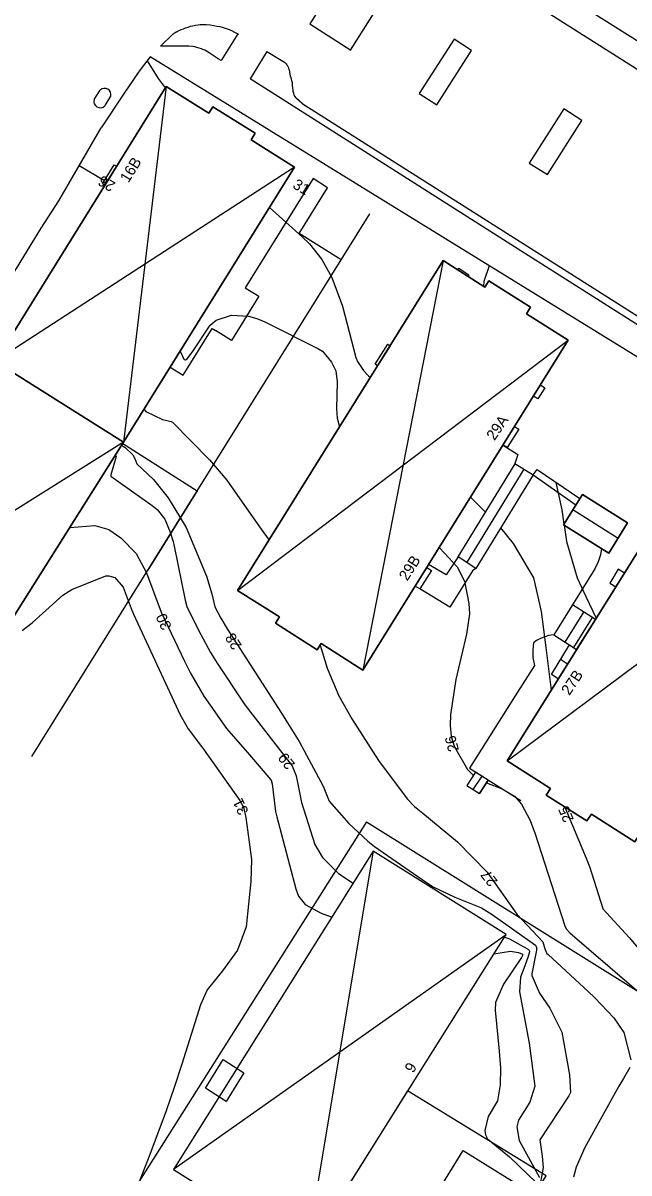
# Model space of a CAD drawing. Extents: x 67169 to 69652, y 20189 to 22818.
# Drawn here: x 69252.8 to 69308.9, y 21145.5 to 21251.9 of the extents above; entities that cross this region are included whole.
import ezdxf

# ---------------------------------------------------------------- set-up
doc = ezdxf.new("R2010")
doc.units = 0
for name, color, linetype in [('BYGGNAD_HUSLIV', 7, 'Continuous'), ('BYGGNAD_HUSLIV 11', 7, 'Continuous'), ('BYGGNADSDETALJER', 7, 'Continuous'), ('BYGGNADSDETALJER 19', 7, 'Continuous'), ('BYGGNADSSYMBOLER', 7, 'Continuous'), ('BYGGNADSSYMBOLER 30', 7, 'Continuous'), ('HOJDKURVOR_2014', 7, 'Continuous'), ('HOJDKURVOR_2014 5M', 7, 'Continuous'), ('HOJDKURVOR_TEXTER_2014', 7, 'Continuous'), ('Instruktioner', 7, 'Continuous'), ('MUR_STAKET', 7, 'Continuous'), ('MUR_STAKET_SYMBOL', 7, 'Continuous'), ('Std_Ritningsstämpel', 7, 'Continuous'), ('VAGAR 121', 7, 'Continuous'), ('VAGAR 123', 7, 'Continuous')]:
    doc.layers.add(name, color=color, linetype=linetype)

msp = doc.modelspace()

# ---------------------------------------------------------------- linework, layer by layer
at = {"layer": 'BYGGNAD_HUSLIV'}
for points in [[(69266.07, 21246.03), (69270.03, 21243.54), (69270.4, 21244.14), (69274.3, 21241.69), (69273.93, 21241.1), (69277.96, 21238.56), (69262.14, 21213.11), (69250.25, 21220.58), (69266.07, 21246.03)], [(69291.69, 21229.91), (69295.55, 21227.45), (69295.93, 21228.04), (69299.78, 21225.59), (69299.4, 21225), (69303.27, 21222.55), (69284.27, 21192.03), (69280.4, 21194.49), (69280.03, 21193.9), (69276.18, 21196.35), (69276.56, 21196.94), (69272.69, 21199.4), (69291.69, 21229.91)], [(69243.03, 21209.08), (69250.25, 21220.58), (69262.14, 21213.11), (69246.7, 21188.62), (69243.05, 21190.91)], [(69316.67, 21214.12), (69320.72, 21211.55), (69321.12, 21212.18), (69324.91, 21209.84), (69324.48, 21209.17), (69328.5, 21206.63), (69309.43, 21176.14), (69305.4, 21178.7), (69304.99, 21178.06), (69301.22, 21180.45), (69301.63, 21181.08), (69297.6, 21183.63), (69316.67, 21214.12)], [(69304.57, 21208.28), (69308.75, 21205.64), (69307.01, 21202.84), (69302.83, 21205.47), (69304.57, 21208.28)], [(69271.34, 21156), (69273.27, 21154.75), (69271.64, 21152.09), (69269.7, 21153.33), (69271.34, 21156)], [(69293.56, 21147.57), (69301.05, 21142.9), (69292.91, 21129.74), (69285.43, 21134.41), (69293.56, 21147.57)]]:
    msp.add_lwpolyline(points, dxfattribs=at)
at = {"layer": 'BYGGNAD_HUSLIV 11'}
for points in [[(69266.07, 21246.03), (69270.03, 21243.54), (69270.4, 21244.14), (69274.3, 21241.69), (69273.93, 21241.1), (69277.96, 21238.56), (69262.14, 21213.11), (69250.25, 21220.58), (69266.07, 21246.03)], [(69291.69, 21229.91), (69295.55, 21227.45), (69295.93, 21228.04), (69299.78, 21225.59), (69299.4, 21225), (69303.27, 21222.55), (69284.27, 21192.03), (69280.4, 21194.49), (69280.03, 21193.9), (69276.18, 21196.35), (69276.56, 21196.94), (69272.69, 21199.4), (69291.69, 21229.91)], [(69243.03, 21209.08), (69250.25, 21220.58), (69262.14, 21213.11), (69246.7, 21188.62), (69243.05, 21190.91)], [(69316.67, 21214.12), (69320.72, 21211.55), (69321.12, 21212.18), (69324.91, 21209.84), (69324.48, 21209.17), (69328.5, 21206.63), (69309.43, 21176.14), (69305.4, 21178.7), (69304.99, 21178.06), (69301.22, 21180.45), (69301.63, 21181.08), (69297.6, 21183.63), (69316.67, 21214.12)]]:
    msp.add_lwpolyline(points, dxfattribs=at)
at = {"layer": 'BYGGNADSDETALJER'}
msp.add_line((69305.49, 21196.88), (69303.76, 21194.11), dxfattribs=at)
for points in [[(69261.27, 21238.77), (69261.48, 21238.64), (69260.38, 21236.88), (69260.18, 21237.01), (69261.27, 21238.77)], [(69293.15, 21229.21), (69294.08, 21228.6), (69293.99, 21228.45), (69293.05, 21229.05), (69293.15, 21229.21)], [(69285.42, 21220.34), (69286.57, 21222.18), (69286.79, 21222.04), (69285.63, 21220.18), (69285.42, 21220.34)], [(69301.09, 21218.15), (69300.45, 21217.11), (69300.04, 21217.37), (69300.69, 21218.42), (69301.09, 21218.15)], [(69297.6, 21212.61), (69297.23, 21212.85), (69298.3, 21214.56), (69298.68, 21214.33), (69297.6, 21212.61)], [(69298.33, 21211.13), (69300.02, 21210.09), (69294.72, 21201.42), (69293.07, 21202.49), (69298.34, 21211.12)], [(69289.11, 21199.8), (69290.17, 21201.5), (69290.61, 21201.23), (69289.55, 21199.53), (69289.11, 21199.8)], [(69307.67, 21199.74), (69308.46, 21201), (69307.89, 21201.35), (69307.12, 21200.08), (69307.67, 21199.74)], [(69304.04, 21193.94), (69305.77, 21196.7), (69303.65, 21198.06), (69301.92, 21195.27), (69304.04, 21193.94)], [(69303.37, 21194.36), (69304.04, 21193.94), (69302.33, 21191.2), (69301.7, 21191.61), (69303.37, 21194.36)], [(69295.87, 21181.84), (69294.7, 21182.58), (69293.88, 21181.34), (69295.07, 21180.61), (69295.87, 21181.84)]]:
    msp.add_lwpolyline(points, dxfattribs=at)
at = {"layer": 'BYGGNADSDETALJER 19'}
msp.add_line((69305.49, 21196.88), (69303.76, 21194.11), dxfattribs=at)
for points in [[(69298.33, 21211.13), (69300.02, 21210.09), (69294.72, 21201.42), (69293.07, 21202.49), (69298.34, 21211.12)], [(69304.04, 21193.94), (69305.77, 21196.7), (69303.65, 21198.06), (69301.92, 21195.27), (69304.04, 21193.94)], [(69295.87, 21181.84), (69294.7, 21182.58), (69293.88, 21181.34), (69295.07, 21180.61), (69295.87, 21181.84)]]:
    msp.add_lwpolyline(points, dxfattribs=at)
at = {"layer": 'BYGGNADSSYMBOLER'}
for p, q in [((69266.07, 21246.03), (69262.14, 21213.11)), ((69277.96, 21238.56), (69250.25, 21220.58)), ((69291.69, 21229.91), (69284.27, 21192.03)), ((69272.69, 21199.4), (69303.27, 21222.55)), ((69293.89, 21201.95), (69299.18, 21210.61)), ((69303.7, 21206.88), (69307.88, 21204.24)), ((69297.6, 21183.63), (69328.5, 21206.63)), ((69293.89, 21201.95), (69293.89, 21201.95)), ((69302.98, 21194.6), (69304.71, 21197.38)), ((69302.98, 21194.6), (69302.98, 21194.6)), ((69303.19, 21192.57), (69302.54, 21192.99)), ((69303.18, 21192.57), (69303.18, 21192.57)), ((69294.47, 21180.98), (69295.29, 21182.21)), ((69294.47, 21180.98), (69294.47, 21180.98)), ((69285.23, 21175.26), (69279.02, 21138.12)), ((69266.75, 21145.84), (69297.52, 21167.57))]:
    msp.add_line(p, q, dxfattribs=at)
msp.add_lwpolyline([(69262.14, 21213.11), (69243.04, 21201.16), (69234.83, 21196.03)], dxfattribs=at)
at = {"layer": 'BYGGNADSSYMBOLER 30'}
for p, q in [((69266.07, 21246.03), (69262.14, 21213.11)), ((69277.96, 21238.56), (69250.25, 21220.58)), ((69291.69, 21229.91), (69284.27, 21192.03)), ((69272.69, 21199.4), (69303.27, 21222.55)), ((69297.6, 21183.63), (69328.5, 21206.63)), ((69285.23, 21175.26), (69279.02, 21138.12)), ((69266.75, 21145.84), (69297.52, 21167.57))]:
    msp.add_line(p, q, dxfattribs=at)
msp.add_lwpolyline([(69262.14, 21213.11), (69243.04, 21201.16), (69234.83, 21196.03)], dxfattribs=at)
at = {"layer": 'HOJDKURVOR_2014'}
for p, q in [((69258.03, 21238.7), (69260.38, 21237.33)), ((69260.58, 21237.21), (69260.59, 21237.21))]:
    msp.add_line(p, q, dxfattribs=at)
for points in [[(69295.94, 21229.43), (69295.46, 21227.97), (69295.42, 21227.54)], [(69267.37, 21221.52), (69267.7, 21220.79), (69267.74, 21220.75), (69267.86, 21220.73), (69268.03, 21220.81), (69268.5, 21221.48), (69270.15, 21223.94), (69270.71, 21224.4), (69272.12, 21224.86), (69273.69, 21224.77), (69274.45, 21224.55), (69275.19, 21224.26), (69280.17, 21221.76), (69280.54, 21221.52), (69281.38, 21220.53), (69281.76, 21219.71), (69281.88, 21218.7), (69281.82, 21216.2), (69281.9, 21215.32), (69282.12, 21214.54)], [(69264.03, 21216.15), (69264.2, 21215.94), (69265.73, 21215.22), (69266.54, 21215.03), (69266.65, 21214.97), (69270.09, 21211.48), (69271.7, 21209.59), (69273.11, 21207.55), (69274.86, 21205.07), (69275.59, 21204.04)], [(69261.96, 21212.82), (69262.28, 21212.61), (69263.01, 21211.94), (69263.18, 21211.6), (69263.38, 21211.1), (69264.91, 21209.67), (69266.26, 21207.97), (69267.94, 21205.21), (69269.8, 21200.7), (69270.29, 21199.09), (69270.59, 21197.89), (69271.14, 21196.83), (69271.73, 21195.84), (69276.74, 21188.03), (69277.16, 21187.38), (69278.39, 21185.42), (69280.6, 21181.27), (69281.16, 21179.89), (69282.97, 21177.82), (69284.72, 21176.19), (69285.36, 21175.71), (69290.14, 21172.36), (69290.76, 21171.96), (69292.77, 21171.01), (69295.24, 21170.02), (69296.24, 21169.42), (69300.23, 21166.56), (69300.34, 21166.34), (69300.34, 21166.1), (69299.89, 21163.92), (69299.89, 21163.77), (69300.6, 21162.14), (69301.56, 21160.75), (69302.67, 21158.53), (69303.39, 21154.56), (69303.46, 21152.93), (69303.32, 21152.64), (69300.65, 21148.55), (69300.86, 21147.06), (69300.95, 21146.01), (69300.59, 21144.09)], [(69261.38, 21211.9), (69261.43, 21211.84), (69261.44, 21211.81), (69261.44, 21211.78), (69260.95, 21210.1), (69260.96, 21209.98), (69264.78, 21207.25), (69265.23, 21206.89), (69265.96, 21206), (69266.46, 21204.78), (69266.71, 21203.93), (69266.81, 21203.5), (69267.82, 21198.49), (69267.98, 21197.92), (69269.06, 21195.71), (69270.17, 21193.66), (69270.78, 21192.66), (69273.35, 21188.8), (69276, 21185.38), (69277.74, 21183.16), (69278.09, 21182.24), (69278.6, 21179.76), (69279.84, 21175.88), (69280.55, 21174.68), (69282, 21173.2), (69283.37, 21172.3)], [(69302.13, 21209.39), (69302.68, 21206.85), (69302.86, 21205.54)], [(69302.88, 21205.44), (69303.09, 21203.92), (69304.09, 21200.55), (69304.88, 21198.84), (69305.85, 21196.83)], [(69291.32, 21203.36), (69291.39, 21203.3), (69292.98, 21201.58), (69293.67, 21200.24), (69294.08, 21198.18), (69294.12, 21197.23), (69293.86, 21195.34), (69292.88, 21191.16), (69292.36, 21187.91), (69292.33, 21186.89), (69292.43, 21185.88), (69292.74, 21184.93), (69293.95, 21182.83), (69294.41, 21182.35), (69294.51, 21182.29)], [(69252.76, 21195.69), (69253.69, 21196.4), (69256.51, 21198.95), (69257.36, 21199.48), (69260.49, 21200.73), (69260.77, 21200.75), (69261.32, 21200.58), (69262.09, 21199.68), (69262.85, 21197.71), (69263.07, 21197.19), (69267.18, 21188.27), (69267.36, 21187.89), (69268.12, 21186.6), (69269.36, 21184.94), (69269.53, 21184.7), (69272.89, 21179.94), (69272.96, 21179.82), (69273.22, 21179.33), (69273.46, 21178.38), (69273.97, 21174.51), (69273.92, 21172.47), (69273.49, 21168.27), (69272.66, 21166.1), (69271.29, 21164.2), (69269.87, 21162.43), (69269.25, 21161.06), (69267.52, 21155.57), (69266.81, 21153.39), (69266.07, 21151.23), (69264.48, 21146.95), (69262.78, 21142.63)], [(69280.31, 21194.34), (69280.98, 21192.19), (69282.05, 21189.64), (69283.25, 21187.51), (69285.7, 21183.67), (69288.36, 21180.1), (69289.03, 21179.39), (69289.81, 21178.77), (69293.01, 21176.14), (69295.75, 21173.33), (69298.5, 21169.45), (69300.91, 21166.89), (69301.11, 21166.24), (69301.29, 21165.81), (69301.4, 21165.69), (69305.11, 21162.28), (69305.73, 21161.69), (69307.48, 21159.86), (69308.41, 21158.5), (69309.05, 21155.95)], [(69295.71, 21181.6), (69297.15, 21181.02), (69298.29, 21180.35), (69298.93, 21179.61), (69299.74, 21178.09), (69299.97, 21177.53), (69300.17, 21176.97), (69302.96, 21168.37), (69303.08, 21168.09), (69303.42, 21167.7), (69310.86, 21161.3), (69311.83, 21160.38), (69313.34, 21158.58), (69313.95, 21157.8), (69314.13, 21157.5), (69314.22, 21157.19), (69314.21, 21157.03), (69313.63, 21155.67), (69313.08, 21154.22), (69313.05, 21153.66), (69313.46, 21152.57), (69313.93, 21151.91)], [(69297.36, 21167.32), (69297.84, 21167.15), (69299.59, 21166.17), (69299.62, 21166.14), (69299.69, 21166.01), (69299.69, 21165.96), (69299.54, 21165.44), (69299.16, 21164.42), (69298.86, 21163.62), (69298.75, 21162.26), (69299.65, 21157.51), (69300.17, 21153.53), (69299.7, 21152.05), (69298.67, 21150.38), (69298.51, 21149.76), (69298.72, 21148.49), (69300.61, 21145.06)], [(69308.97, 21155.26), (69308.37, 21154.24), (69307.95, 21153.53), (69304.8, 21147.85), (69304.01, 21146.04), (69303.76, 21145.09)]]:
    msp.add_lwpolyline(points, dxfattribs=at)
at = {"layer": 'HOJDKURVOR_2014 5M'}
for points in [[(69264.32, 21248.39), (69265.33, 21246.77), (69265.99, 21245.9)], [(69275.64, 21234.84), (69278.66, 21232.12), (69279.32, 21231.46), (69280.48, 21230), (69281.4, 21228.36), (69282.37, 21225.71), (69283.63, 21220.96), (69283.77, 21220.58), (69284.34, 21219.73), (69284.94, 21219.07)], [(69294.23, 21208.03), (69294.86, 21207.39), (69295.61, 21206.65)], [(69257.17, 21205.22), (69259.49, 21205.41), (69260.77, 21205.03), (69261.89, 21204.27), (69263.3, 21202.82), (69264.26, 21201.03), (69265.6, 21197.39), (69267.78, 21192.84), (69268.34, 21191.75), (69269.55, 21189.62), (69271.65, 21186.61), (69273.79, 21184.17), (69275.76, 21181.87), (69275.79, 21181.83), (69275.88, 21181.5), (69276.2, 21178.95), (69276.32, 21178.43), (69278.06, 21171.79), (69278.33, 21171.09), (69278.93, 21170.34), (69280.42, 21169.52), (69281.34, 21169.2), (69281.41, 21169.18)], [(69297.01, 21205.18), (69298.16, 21203.75), (69300.05, 21200.56), (69300.77, 21197.43), (69301.19, 21194.11), (69301.67, 21190.15)], [(69302.95, 21179.35), (69304.93, 21174.61), (69305.23, 21173.85), (69306.45, 21169.96), (69306.46, 21169.94), (69308.91, 21167.29), (69310.39, 21165.51), (69311.09, 21164.58), (69315.18, 21158.97), (69315.21, 21158.93), (69315.36, 21158.76), (69316.11, 21158.38), (69316.71, 21158.2)], [(69296.38, 21165.76), (69297.92, 21166), (69298.67, 21165.9), (69299.02, 21165.73), (69299.05, 21165.67), (69298.95, 21165.42), (69297.28, 21162.96), (69296.55, 21161.27), (69296.49, 21160.54), (69296.87, 21156.77), (69297.01, 21155.2), (69296.97, 21153.64), (69296.72, 21152.18), (69295.86, 21150.73), (69295.55, 21149.41), (69295.61, 21149.01), (69295.8, 21148.66), (69297.82, 21146.97), (69300.31, 21144.61)]]:
    msp.add_lwpolyline(points, dxfattribs=at)
at = {"layer": 'MUR_STAKET'}
for p, q in [((69300.02, 21210.09), (69303.97, 21207.32)), ((69294.7, 21182.58), (69293.88, 21181.34)), ((69295.87, 21181.84), (69295.07, 21180.61)), ((69284.59, 21177.99), (69263.19, 21144.09))]:
    msp.add_line(p, q, dxfattribs=at)
for points in [[(69296.1, 21258.84), (69302.52, 21254.78), (69308.5, 21251), (69318.67, 21244.59), (69325.22, 21240.45), (69336.99, 21232.99), (69342.36, 21229.57), (69352.6, 21223.18), (69355.62, 21221.19), (69360.68, 21217.97), (69370.52, 21211.77), (69376.01, 21208.27), (69380.2, 21208.31), (69385.38, 21216.32)], [(69253.66, 21184.04), (69269.07, 21208.8), (69284.9, 21234.23)], [(69266.45, 21220.05), (69267.64, 21219.31), (69270.33, 21223.64), (69270.63, 21223.46)], [(69262.06, 21212.98), (69268.95, 21208.6), (69264.38, 21201.28)], [(69305.73, 21201.39), (69301.92, 21195.27), (69301.43, 21195.22), (69300.76, 21194.97), (69300.33, 21194.76), (69300.04, 21194.53), (69299.98, 21193.87), (69299.98, 21193.2), (69300.13, 21192.46), (69298.36, 21189.65), (69294.13, 21182.95), (69298.87, 21179.95)], [(69284.59, 21177.99), (69309.53, 21162.41), (69316.52, 21157.9)]]:
    msp.add_lwpolyline(points, dxfattribs=at)
at = {"layer": 'MUR_STAKET_SYMBOL'}
for p, q in [((69308.5, 21251), (69308.5, 21251)), ((69308.5, 21251), (69308.5, 21251)), ((69281.24, 21228.36), (69281.24, 21228.36)), ((69269.76, 21222.73), (69269.76, 21222.73)), ((69270.63, 21223.46), (69270.63, 21223.46)), ((69269.11, 21221.67), (69269.11, 21221.67)), ((69268.52, 21220.73), (69268.52, 21220.73)), ((69266.79, 21219.84), (69266.79, 21219.84)), ((69267.85, 21219.66), (69267.85, 21219.66)), ((69267.46, 21219.42), (69267.46, 21219.42)), ((69273.25, 21215.52), (69273.25, 21215.52)), ((69263.18, 21212.27), (69263.18, 21212.27)), ((69264.46, 21211.45), (69264.46, 21211.45)), ((69265.76, 21210.63), (69265.76, 21210.63)), ((69266.99, 21209.85), (69266.99, 21209.85)), ((69268.31, 21209), (69268.31, 21209)), ((69301.56, 21209.01), (69301.56, 21209.01)), ((69268.33, 21207.62), (69268.33, 21207.62)), ((69267.58, 21206.41), (69267.58, 21206.41)), ((69266.79, 21205.15), (69266.79, 21205.15)), ((69265.99, 21203.87), (69265.99, 21203.87)), ((69266.42, 21204.54), (69266.42, 21204.54)), ((69265.21, 21202.61), (69265.21, 21202.61)), ((69264.38, 21201.28), (69264.38, 21201.28)), ((69305.73, 21201.39), (69305.73, 21201.39)), ((69304.96, 21200.16), (69304.96, 21200.16)), ((69304.14, 21198.85), (69304.14, 21198.85)), ((69303.34, 21197.56), (69303.34, 21197.56)), ((69302.6, 21196.38), (69302.6, 21196.38)), ((69301.39, 21195.21), (69301.39, 21195.21)), ((69300.23, 21194.68), (69300.23, 21194.68)), ((69299.98, 21193.81), (69299.98, 21193.81)), ((69258.57, 21191.93), (69258.57, 21191.93)), ((69299.98, 21192.23), (69299.98, 21192.23)), ((69299.16, 21190.94), (69299.16, 21190.94)), ((69298.38, 21189.68), (69298.38, 21189.68)), ((69297.57, 21188.41), (69297.57, 21188.41)), ((69296.8, 21187.19), (69296.8, 21187.19)), ((69295.99, 21185.89), (69295.99, 21185.89)), ((69295.18, 21184.62), (69295.18, 21184.62)), ((69294.39, 21183.36), (69294.39, 21183.36)), ((69293.88, 21181.34), (69293.88, 21181.34)), ((69294.37, 21182.08), (69294.37, 21182.08)), ((69295.53, 21181.32), (69295.53, 21181.32)), ((69295.07, 21180.61), (69295.07, 21180.61)), ((69297.28, 21180.94), (69297.28, 21180.94)), ((69298.51, 21180.16), (69298.51, 21180.16)), ((69281.84, 21173.6), (69281.84, 21173.6)), ((69292.96, 21172.76), (69292.96, 21172.76)), ((69302.19, 21166.99), (69302.19, 21166.99)), ((69275.67, 21163.79), (69275.67, 21163.79)), ((69269.18, 21153.59), (69269.18, 21153.59))]:
    msp.add_line(p, q, dxfattribs=at)
at = {"layer": 'Std_Ritningsstämpel'}
for points in [[(69266.07, 21246.03), (69250.25, 21220.58), (69262.14, 21213.11), (69277.96, 21238.56), (69273.93, 21241.1), (69274.3, 21241.69), (69270.4, 21244.14), (69270.03, 21243.54)], [(69291.69, 21229.91), (69272.69, 21199.4), (69276.56, 21196.94), (69276.18, 21196.35), (69280.03, 21193.9), (69280.4, 21194.49), (69284.27, 21192.03), (69303.27, 21222.55), (69299.4, 21225), (69299.78, 21225.59), (69295.93, 21228.04), (69295.55, 21227.45)], [(69250.25, 21220.58), (69243.03, 21209.08), (69234.83, 21196.03), (69243.05, 21190.91), (69246.7, 21188.62), (69262.14, 21213.11)], [(69316.67, 21214.12), (69297.6, 21183.63), (69301.63, 21181.08), (69301.22, 21180.45), (69304.99, 21178.06), (69305.4, 21178.7), (69309.43, 21176.14), (69328.5, 21206.63), (69324.48, 21209.17), (69324.91, 21209.84), (69321.12, 21212.18), (69320.72, 21211.55)], [(69304.57, 21208.28), (69302.83, 21205.47), (69307.01, 21202.84), (69308.75, 21205.64)], [(69266.76, 21145.82), (69279.02, 21138.11), (69297.52, 21167.57), (69285.23, 21175.26)], [(69279.02, 21138.11), (69291.73, 21130.03), (69301.23, 21145.21), (69288.39, 21153.08)]]:
    msp.add_lwpolyline(points, close=True, dxfattribs=at)
at = {"layer": 'VAGAR 121'}
for p, q in [((69272.7, 21250.9), (69271.15, 21248.42)), ((69376.14, 21179.98), (69264.59, 21248.76)), ((69275.39, 21249.27), (69273.84, 21246.73)), ((69298.62, 21230.97), (69273.84, 21246.73)), ((69259.43, 21244.82), (69259.97, 21245.67)), ((69260.94, 21245.12), (69260.4, 21244.25)), ((69310.95, 21223.94), (69278.89, 21244.25)), ((69331.52, 21210.09), (69298.62, 21230.97))]:
    msp.add_line(p, q, dxfattribs=at)
for points in [[(69313.16, 21245.38), (69298.29, 21254.81), (69295.63, 21256.45), (69293.87, 21257.57), (69257.76, 21280.45), (69248.82, 21286.11), (69242.96, 21289.82), (69226.82, 21300.08), (69172.15, 21334.79)], [(69283.11, 21249.37), (69286.27, 21254.38), (69282.55, 21256.84), (69279.37, 21251.81), (69283.15, 21249.4)], [(69265.56, 21249.75), (69266.7, 21250.85), (69266.76, 21250.9), (69266.82, 21250.95), (69266.88, 21250.99), (69266.99, 21251.07), (69267.09, 21251.12), (69267.19, 21251.17), (69267.35, 21251.25), (69267.48, 21251.3), (69267.68, 21251.37), (69267.87, 21251.44), (69268.11, 21251.52), (69268.32, 21251.59), (69268.5, 21251.63), (69268.66, 21251.67), (69268.8, 21251.7), (69269.05, 21251.74), (69269.23, 21251.76), (69269.37, 21251.77), (69269.58, 21251.77), (69269.78, 21251.76), (69270.15, 21251.72), (69270.48, 21251.67), (69270.77, 21251.62), (69271.03, 21251.56), (69271.25, 21251.51), (69271.63, 21251.39), (69271.91, 21251.29), (69272.11, 21251.2), (69272.41, 21251.06), (69272.7, 21250.9), (69272.76, 21250.86)], [(69289.48, 21245.36), (69291.1, 21244.32), (69294.33, 21249.34), (69292.7, 21250.39), (69289.48, 21245.36)], [(69271.15, 21248.42), (69270.9, 21248.57), (69270.04, 21249.14), (69269.82, 21249.28), (69269.65, 21249.37), (69269.52, 21249.43), (69269.33, 21249.51), (69269.13, 21249.58), (69268.92, 21249.64), (69268.72, 21249.68), (69268.53, 21249.71), (69268.17, 21249.74), (69267.85, 21249.76), (69267.28, 21249.77), (69266.42, 21249.74), (69265.99, 21249.74), (69265.56, 21249.75)], [(69264.59, 21248.76), (69263.78, 21247.68), (69263.38, 21247.14), (69262.99, 21246.59), (69262.24, 21245.51), (69260.08, 21242.21)], [(69275.39, 21249.27), (69277.01, 21248.27), (69277.05, 21248.24), (69277.12, 21248.17), (69277.19, 21248.11), (69277.24, 21248.04), (69277.28, 21247.97), (69277.32, 21247.9), (69277.35, 21247.83), (69277.4, 21247.7), (69277.44, 21247.58), (69277.49, 21247.36), (69277.56, 21247.02), (69277.6, 21246.86), (69277.65, 21246.7), (69277.68, 21246.59), (69277.7, 21246.49), (69277.72, 21246.38), (69277.74, 21246.18), (69277.77, 21245.83), (69277.79, 21245.7), (69277.8, 21245.59), (69277.82, 21245.49), (69277.84, 21245.41), (69277.86, 21245.34), (69277.91, 21245.23), (69277.95, 21245.14), (69277.98, 21245.09), (69278.04, 21245), (69278.08, 21244.96), (69278.12, 21244.93), (69278.89, 21244.25)], [(69299.66, 21238.94), (69301.34, 21237.87), (69304.53, 21242.89), (69302.86, 21243.95), (69299.66, 21238.94)], [(69243.01, 21214.4), (69243.03, 21214.42), (69245.05, 21217.65), (69246.56, 21220.07), (69247.45, 21221.54), (69250.73, 21226.83), (69251.44, 21227.94), (69252.23, 21229.19), (69254.53, 21232.92), (69256.14, 21235.45), (69260.08, 21242.21)]]:
    msp.add_lwpolyline(points, dxfattribs=at)
for centre, major_axis, ratio, start_param, end_param in [((69260.39, 21245.28), (-0.283, -0.503), 0.999952, 1.814367, 4.468818), ((69259.97, 21244.63), (0.289, 0.497), 0.999237, 1.769025, 4.51416)]:
    msp.add_ellipse(centre, major_axis=major_axis, ratio=ratio, start_param=start_param, end_param=end_param, dxfattribs=at)
at = {"layer": 'VAGAR 123'}
for points in [[(69282.27, 21229.99), (69278.37, 21232.42), (69281.01, 21236.66), (69279.66, 21237.51), (69273.38, 21227.4), (69274.65, 21226.61), (69272.11, 21222.53), (69270.63, 21223.46)], [(69297.23, 21212.85), (69298.61, 21211.97), (69298.33, 21211.13)], [(69300.02, 21210.09), (69300.4, 21210.58), (69304.32, 21207.89)], [(69293.07, 21202.49), (69291.96, 21200.83), (69290.34, 21201.78)], [(69305.73, 21201.39), (69306.03, 21201.99), (69306.28, 21202.73), (69306.38, 21203.23)], [(69294.72, 21201.42), (69294.4, 21201.22), (69292.32, 21197.84), (69289.55, 21199.53)]]:
    msp.add_lwpolyline(points, dxfattribs=at)

# ---------------------------------------------------------------- texts
at = {"layer": 'HOJDKURVOR_TEXTER_2014'}
for s, rotation, p in [('26', 149.7346, (69261.46, 21237.09)), ('30', 115.6259, (69266.62, 21196.04)), ('28', 122.6638, (69273.11, 21194.31)), ('26', 105.0104, (69293.17, 21184.62)), ('29', 128.256, (69278.05, 21183.32)), ('31', 116.3084, (69273.73, 21178.93)), ('25', 112.6626, (69303.8, 21178.19)), ('27', 128.0519, (69296.79, 21172.49))]:
    msp.add_text(s, height=1, rotation=rotation, dxfattribs=at).set_placement(p)
at = {"layer": 'Instruktioner'}
for s, rotation, p in [('16B', 58.2472, (69262.59, 21237.05)), ('31', 329.3884, (69277.7, 21236.68)), ('29A', 55.7578, (69296.44, 21213.2)), ('29B', 57.4796, (69288.37, 21200.21)), ('27B', 56.3238, (69303.37, 21189.62)), ('9', 58.4587, (69288.92, 21154.67))]:
    msp.add_text(s, height=1, rotation=rotation, dxfattribs=at).set_placement(p)

doc.saveas('drawing.dxf')
